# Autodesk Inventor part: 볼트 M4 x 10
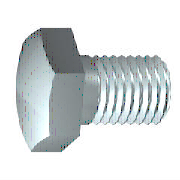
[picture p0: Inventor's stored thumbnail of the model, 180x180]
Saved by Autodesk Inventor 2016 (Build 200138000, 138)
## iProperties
Created: 2012-02
Part Number: 볼트 M4 x 10
Material: 스테인리스강
Description: 6각 머리 나사
Document SubType Name: Modeling
Standard: ISO 4017
Designer: mduedu
Standard Revision: Third edition 1999-08-15
Standards Organization: ISO
Language: ko-KR
Size Designation: M4 x 10
Categories: <MemberInstance><Categories><Category DisplayName="조임쇠" InternalName="e4da775c-781d-43d5-af7c-5136215cf5a6" Mnemonic="FSTN"><Category DisplayName="볼트" InternalN
Density: 8.08 g/cm^3
Appearance: 기본값
IsCustomPart: 0
Author: mduedu
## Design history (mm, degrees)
sketch "스케치1"
  geometry: L1 (0, 3.015)-(0, 2); L2 (2.1, 2)-(10, 2); L3 (10, 2)-(10, 0); L4 (10, 0)-(-0.4, 0); L5 (-2.48, 0)-(12.08, 0) reference; L6 (-0.4, 0)-(-0.4, 3.015); L7 (-0.4, 3.015)-(0, 3.015); L8 (2.1, 2)-(1.67, 2); L9 (1.67, 2)-(0, 2); L10 (0, -0.603)-(0, 3.618) reference
  constraints: 16 end point, 2 collinear, 2 perpendicular, 1 parallel
  dimensions: "d0" = 10 distance between parallel lines of L3 L1 (= NLG); "d1" = 7.9 distance from line of L2.start L3 (= GEL); "d2" = 4 diameter of L2 L4 (= GD); "d9" = 0.4001 distance between parallel lines of L6 L1 (computed from SD); "d10" = 6.03 diameter of L7 L4 (= SD2); "d13" = 0.42952 distance of L2.start L8.end (computed from GAL); "d14" = 4 diameter of L9 L4 (= BDM)
revolve "본체" sketch "스케치1" stored, may be unused: angle "d12" = 90 deg
sketch "스케치2"
  geometry: L1 (0, 4.041)-(3.5, 2.021); L2 (3.5, 2.021)-(3.5, -2.021); L3 (3.5, -2.021)-(0, -4.041); L4 (0, -4.041)-(-3.5, -2.021); L5 (-3.5, -2.021)-(-3.5, 2.021); L6 (-3.5, 2.021)-(0, 4.041); 2 further points
  constraints: 12 end point, 1 coincident, 1 vertical, 11 other
  dimensions: "d11" = 7 distance between parallel lines of L5 L2 (= SW)
extrude "머리" join sketch "스케치2" distance "d3" = 2.4 (= KOH - SD); taper "d4" = 0 deg
sketch "스케치4"
  geometry: L1 (-2.8, 3.5)-(-2.8, 4.041); L2 (-2.8, 4.041)-(-2.487, 4.041); L3 (-2.487, 4.041)-(-2.8, 3.5); L4 (-3.28, 0)-(0.08, 0) reference; L5 (-0.4, 4.041)-(-2.8, 4.041) reference; L6 (-2.8, 2.021)-(-2.8, 4.041) reference
  constraints: 6 end point, 2 collinear, 1 perpendicular, 1 vertical
  dimensions: "d5" = 30 deg angle of L3 L1 (= ANG1); "d19" = 7 diameter of L1.start L4 (= SW0)
revolve "모따기1" sketch "스케치4" stored, may be unused: angle "d21" = 90 deg
workplane "Work Plane1"
body "Solid1"
feature "스레드" dims "d15" = 7.9 (= GEL), "d16" = 0
chamfer "모따기2" distance "d6" = 0.42941 (= -0.5 x SPD + 0.5 x GD); stored, may be unused: second distance "d7" = 0.42952 (computed from GUL), angle "d55" = 45 deg
other parameters: "NLG" = 10 [user parameter; used in 1 equation term], "GD" = 4 (= NND) [user parameter; used in 2 equation terms], "BDM" = 4 (= NND) [user parameter; used in 1 equation term], "KOH" = 2.8 [user parameter; used in 1 equation term], "GEL" = 7.9 [user parameter; used in 2 equation terms], "SW" = 7 [user parameter; used in 2 equation terms], "SW0" = 7 (= SW) [user parameter; used in 1 equation term], "SPD" = 3.14117 (= NND - 1.2269 x PTC) [user parameter; used in 1 equation term], "SD2" = 6.03 [user parameter; used in 2 equation terms], "SD" = 0.4 [user parameter; used in 2 equation terms], "ANG1" = 30 deg [user parameter; used in 1 equation term], "GAL" = 0.42941 (= 0.61345 x PTC) [user parameter; used in 1 equation term], "GUL" = 0.42941 (= 0.61345 x PTC) [user parameter; used in 1 equation term], "d8" = 0, "RR" = 0.2 [user parameter], "d57" = 0, "d58" = 0, "TPU" = 14.28571 (computed from PTC) [user parameter], "GD1" = 3.14117 (= THREADDIA - 1.2269 x PTC) [user parameter], "THREADDIA" = 4 [user parameter; used in 1 equation term], "SDH" = 6.03 (= SD2) [user parameter], "SDHG" = 2.1 [user parameter], "TOA" = 30 deg [user parameter], "PTC" = 0.7 [user parameter; used in 5 equation terms], "NND" = 4 [user parameter; used in 3 equation terms], "E0" = 8.085 [user parameter]
